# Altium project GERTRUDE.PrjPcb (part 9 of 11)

## Sheet WIFI_BLE.SchDoc: WIFI BLE
size A3; Author: Silvio Navaretti; CompanyName: ARDUINO; DrawnBy: Silvio Navaretti; Engineer: Silvio Navaretti; Organization: ARDUINO; SheetNumber: 29; SheetTotal: 51; RevAuthor: Silvio Navaretti
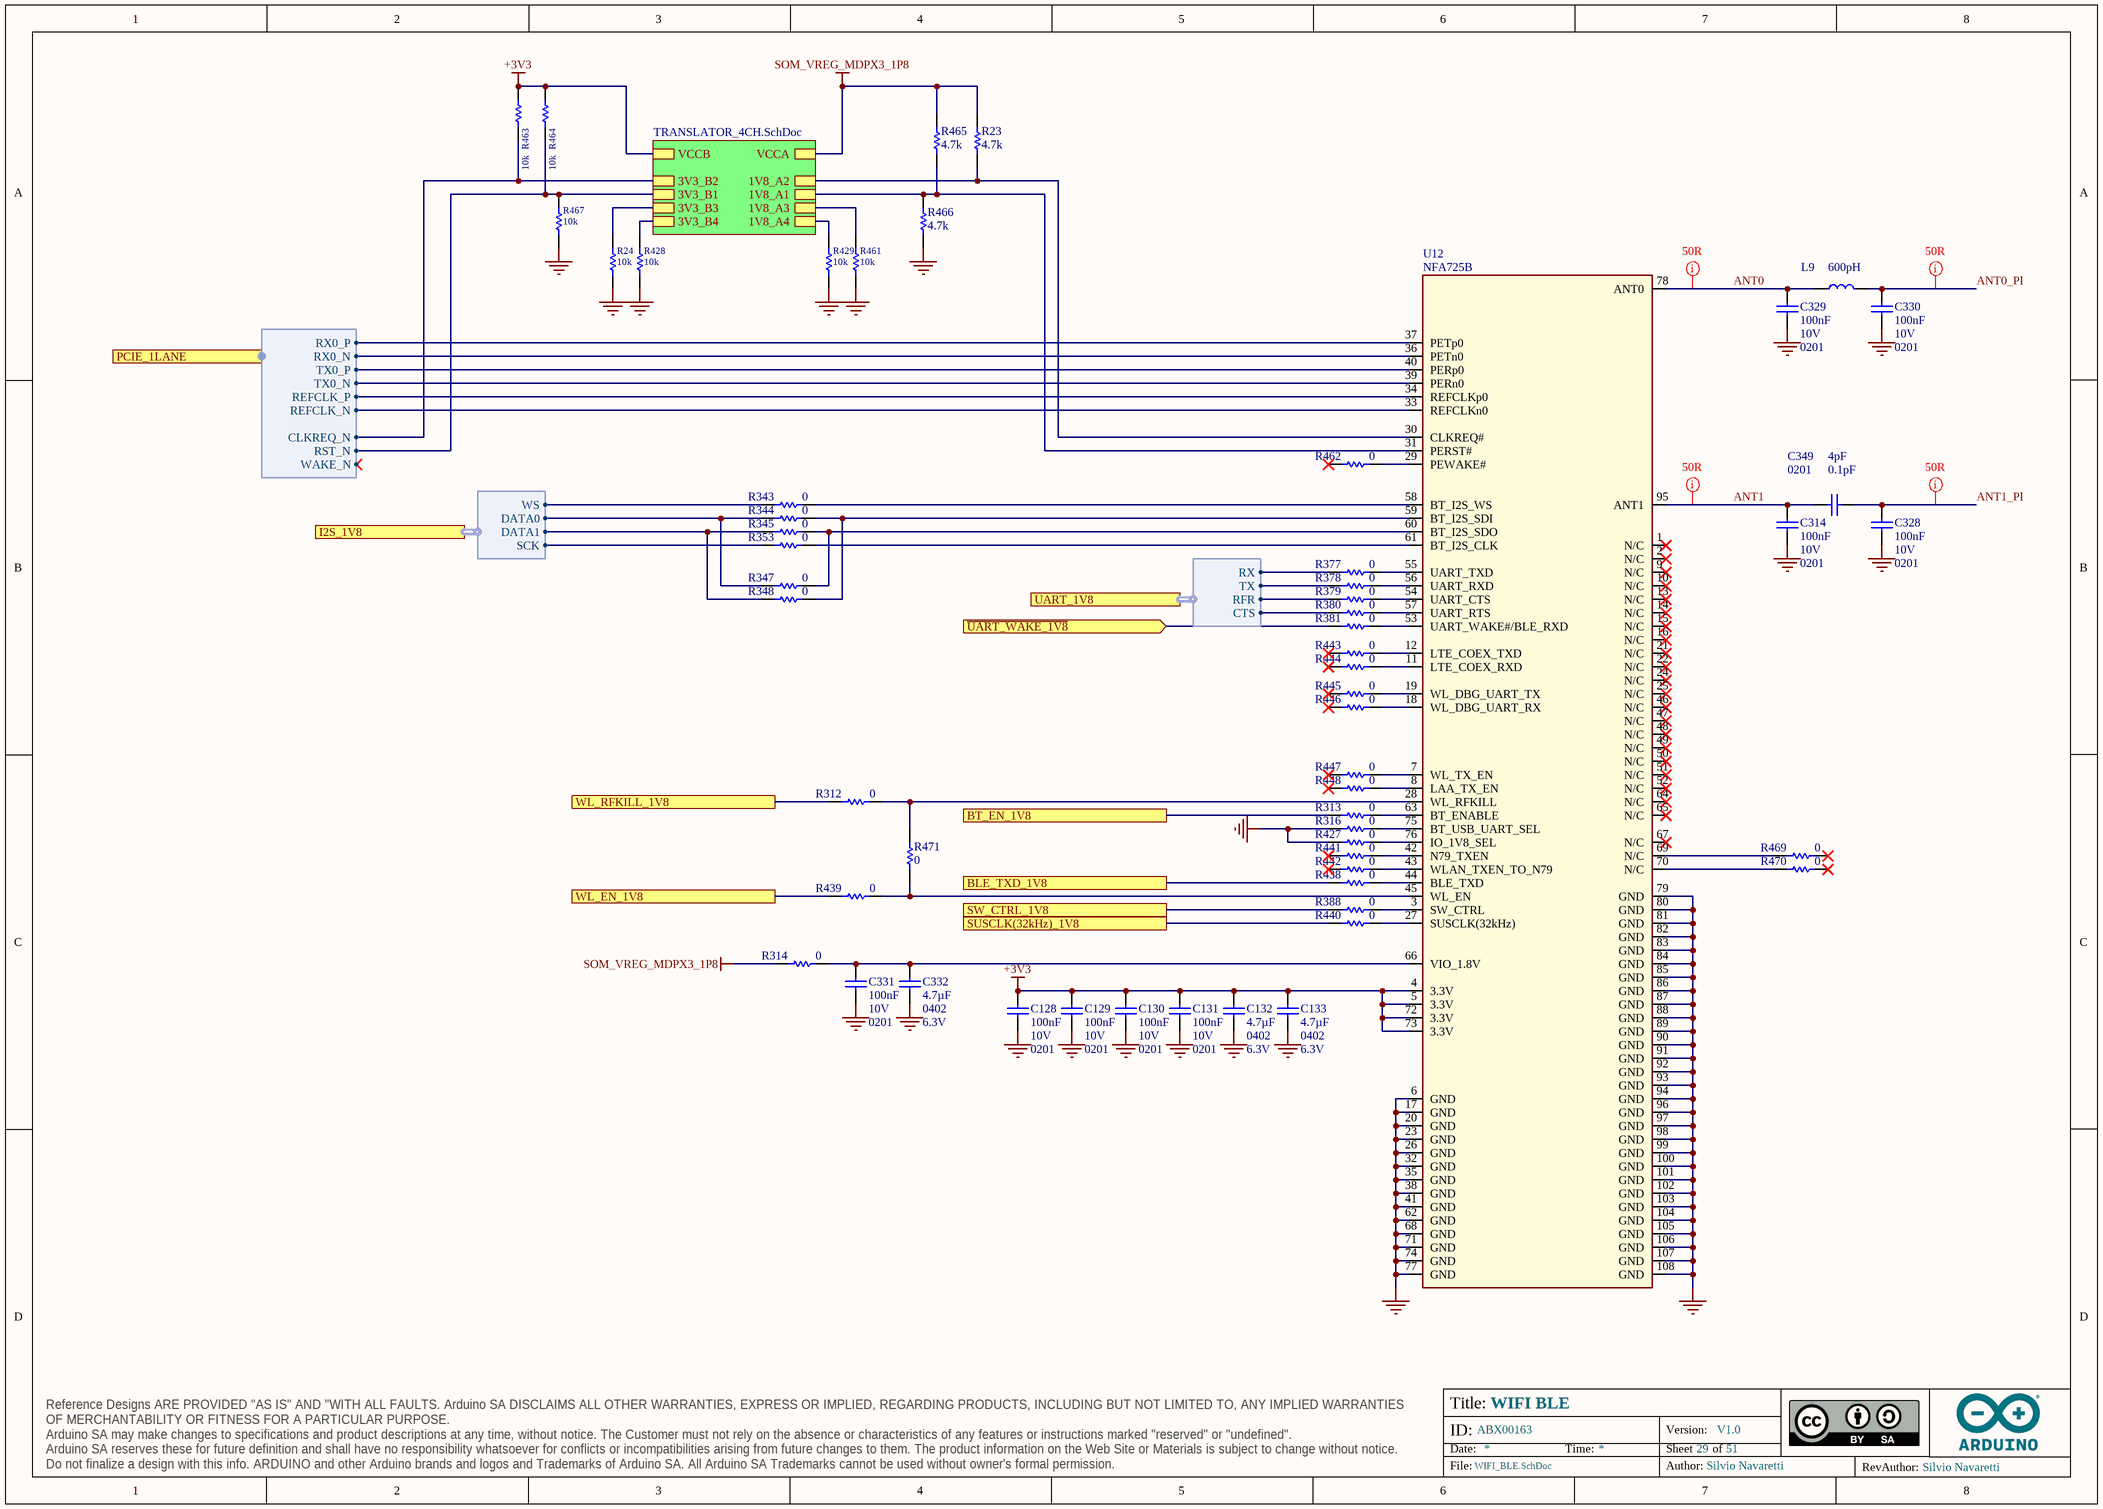
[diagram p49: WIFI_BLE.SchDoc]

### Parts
C128  value 100nF  Voltage: 10V  Case Code (Imperial): 0201  [CAP-0201]  (hidden comment: CL03A104KP3NNNC)
C129  value 100nF  Voltage: 10V  Case Code (Imperial): 0201  [CAP-0201]  (hidden comment: CL03A104KP3NNNC)
C130  value 100nF  Voltage: 10V  Case Code (Imperial): 0201  [CAP-0201]  (hidden comment: CL03A104KP3NNNC)
C131  value 100nF  Voltage: 10V  Case Code (Imperial): 0201  [CAP-0201]  (hidden comment: CL03A104KP3NNNC)
C132  value 4.7µF  Case Code (Imperial): 0402  Voltage: 6.3V  [CAP-0402]  (hidden comment: C1005A475M6R3NT)
C133  value 4.7µF  Case Code (Imperial): 0402  Voltage: 6.3V  [CAP-0402]  (hidden comment: C1005A475M6R3NT)
C314  value 100nF  Voltage: 10V  Case Code (Imperial): 0201  [CAP-0201]  (hidden comment: CL03A104KP3NNNC)
C328  value 100nF  Voltage: 10V  Case Code (Imperial): 0201  [CAP-0201]  (hidden comment: CL03A104KP3NNNC)
C329  value 100nF  Voltage: 10V  Case Code (Imperial): 0201  [CAP-0201]  (hidden comment: CL03A104KP3NNNC)
C330  value 100nF  Voltage: 10V  Case Code (Imperial): 0201  [CAP-0201]  (hidden comment: CL03A104KP3NNNC)
C331  value 100nF  Voltage: 10V  Case Code (Imperial): 0201  [CAP-0201]  (hidden comment: CL03A104KP3NNNC)
C332  value 4.7µF  Case Code (Imperial): 0402  Voltage: 6.3V  [CAP-0402]  (hidden comment: C1005A475M6R3NT)
C349  value 4pF  Case Code (Imperial): 0201  Tolerance: 0.1pF  [CAP-0201]  (hidden comment: GRM0335C1H4R0BA01D)
L9  Inductance: 600pH  [0201DS Coilcraft]  (hidden comment: 0201DS-0N6XKEW)
R23  value 4.7k  [RES-0201]  (hidden comment: RC0201FR-074K7L)
R24  value 10k  [RES-0201]  (hidden comment: RC0201FR-0710KL)
R312  value 0  [RES-0201]  (hidden comment: CRCW02010000Z0ED)
R313  value 0  [RES-0201]  (hidden comment: CRCW02010000Z0ED)
R314  value 0  [RES-0201]  (hidden comment: CRCW02010000Z0ED)
R316  value 0  [RES-0201]  (hidden comment: CRCW02010000Z0ED)
R343  value 0  [RES-0201]  (hidden comment: CRCW02010000Z0ED)
R344  value 0  [RES-0201]  (hidden comment: CRCW02010000Z0ED)
R345  value 0  [RES-0201]  (hidden comment: CRCW02010000Z0ED)
R347  value 0  [RES-0201]  (hidden comment: CRCW02010000Z0ED)
R348  value 0  [RES-0201]  (hidden comment: CRCW02010000Z0ED)
R353  value 0  [RES-0201]  (hidden comment: CRCW02010000Z0ED)
R377  value 0  [RES-0201]  (hidden comment: CRCW02010000Z0ED)
R378  value 0  [RES-0201]  (hidden comment: CRCW02010000Z0ED)
R379  value 0  [RES-0201]  (hidden comment: CRCW02010000Z0ED)
R380  value 0  [RES-0201]  (hidden comment: CRCW02010000Z0ED)
R381  value 0  [RES-0201]  (hidden comment: CRCW02010000Z0ED)
R388  value 0  [RES-0201]  (hidden comment: CRCW02010000Z0ED)
R427  value 0  [RES-0201]  (hidden comment: CRCW02010000Z0ED)
R428  value 10k  [RES-0201]  (hidden comment: RC0201FR-0710KL)
R429  value 10k  [RES-0201]  (hidden comment: RC0201FR-0710KL)
R438  value 0  [RES-0201]  (hidden comment: CRCW02010000Z0ED)
R439  value 0  [RES-0201]  (hidden comment: CRCW02010000Z0ED)
R440  value 0  [RES-0201]  (hidden comment: CRCW02010000Z0ED)
R441  value 0  [RES-0201]  (hidden comment: CRCW02010000Z0ED)
R442  value 0  [RES-0201]  (hidden comment: CRCW02010000Z0ED)
R443  value 0  [RES-0201]  (hidden comment: CRCW02010000Z0ED)
R444  value 0  [RES-0201]  (hidden comment: CRCW02010000Z0ED)
R445  value 0  [RES-0201]  (hidden comment: CRCW02010000Z0ED)
R446  value 0  [RES-0201]  (hidden comment: CRCW02010000Z0ED)
R447  value 0  [RES-0201]  (hidden comment: CRCW02010000Z0ED)
R448  value 0  [RES-0201]  (hidden comment: CRCW02010000Z0ED)
R461  value 10k  [RES-0201]  (hidden comment: RC0201FR-0710KL)
R462  value 0  [RES-0201]  (hidden comment: CRCW02010000Z0ED)
R463  value 10k  [RES-0201]  (hidden comment: RC0201FR-0710KL)
R464  value 10k  [RES-0201]  (hidden comment: RC0201FR-0710KL)
R465  value 4.7k  [RES-0201]  (hidden comment: RC0201FR-074K7L)
R466  value 4.7k  [RES-0201]  (hidden comment: RC0201FR-074K7L)
R467  value 10k  [RES-0201]  (hidden comment: RC0201FR-0710KL)
R469  value 0  [RES-0201]  (hidden comment: CRCW02010000Z0ED)
R470  value 0  [RES-0201]  (hidden comment: CRCW02010000Z0ED)
R471  value 0  [RES-0201]  (hidden comment: CRCW02010000Z0ED)
U12  NFA725B  [NFA725B]

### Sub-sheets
U_TRANSLATOR_4CH = TRANSLATOR_4CH.SchDoc: 1V8_A1, 1V8_A2, 1V8_A3, 1V8_A4, 3V3_B1, 3V3_B2, 3V3_B3, 3V3_B4, VCCA, VCCB

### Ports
BLE_TXD_1V8, BT_EN_1V8, I2S_1V8 (harness SOM_MD_I2S), PCIE_1LANE (harness PCIE_1LANE), SUSCLK(32kHz)_1V8, SW_CTRL_1V8, UART_1V8 (harness SOM_MD_UART_FLCRTL), WL_EN_1V8, WL_RFKILL_1V8, ~{UART_WAKE_1V8} (in)

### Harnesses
SOM_MD_I2S: SCK, WS, DATA0, DATA1
SOM_MD_UART_FLCRTL: TX, CTS, RFR, RX
PCIE_1LANE: RX0_N, RX0_P, TX0_P, TX0_N, REFCLK_N, REFCLK_P, WAKE_N, CLKREQ_N, RST_N

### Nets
+3V3: C128.2 C129.2 C130.2 C131.2 C132.1 C133.1 R463.1 R464.1 U12.4(3.3V) U12.5(3.3V) U12.72(3.3V) U12.73(3.3V) ; sheet U_TRANSLATOR_4CH/VCCB
GND: C128.1 C129.1 C130.1 C131.1 C132.2 C133.2 C314.1 C328.1 C329.1 C330.1 C331.1 C332.2 R24.1 R316.1 R427.1 R428.1 R429.1 R461.1 R466.1 R467.1 U12.6(GND) U12.17(GND) U12.20(GND) U12.23(GND) U12.26(GND) U12.32(GND) U12.35(GND) U12.38(GND) U12.41(GND) U12.62(GND) U12.68(GND) U12.71(GND) U12.74(GND) U12.77(GND) U12.79(GND) U12.80(GND) U12.81(GND) U12.82(GND) U12.83(GND) U12.84(GND) U12.85(GND) U12.86(GND) U12.87(GND) U12.88(GND) U12.89(GND) U12.90(GND) U12.91(GND) U12.92(GND) U12.93(GND) U12.94(GND) U12.96(GND) U12.97(GND) U12.98(GND) U12.99(GND) U12.100(GND) U12.101(GND) U12.102(GND) U12.103(GND) U12.104(GND) U12.105(GND) U12.106(GND) U12.107(GND) U12.108(GND)
SOM_VREG_MDPX3_1P8: R23.2 R314.1 R465.2 ; sheet U_TRANSLATOR_4CH/VCCA
ANT0: C329.2 L9.1 U12.78(ANT0)  [project net ANT0_29]
ANT0_PI: C330.2 L9.2  [project net ANT0_PI_29]
ANT1: C314.2 C349.2 U12.95(ANT1)  [project net ANT1_29]
ANT1_PI: C328.2 C349.1  [project net ANT1_PI_29]
CTS_1V8: R380.1 ; port UART_1V8.CTS
MD_GPIO_54: R312.1 ; port WL_RFKILL_1V8
MD_GPIO_55: R313.1 ; port BT_EN_1V8
MD_GPIO_56: R439.1 ; port WL_EN_1V8
MD_GPIO_65: R381.1 ; port ~{UART_WAKE_1V8}
MD_GPIO_85: R379.1 ; port UART_1V8.RFR
MD_GPIO_86: R378.1 ; port UART_1V8.TX
MD_GPIO_87: R377.1 ; port UART_1V8.RX
MD_GPIO_100: R388.1 ; port SW_CTRL_1V8
MD_GPIO_101: R438.1 ; port BLE_TXD_1V8
MD_LPASS_GPIO_129: R353.1 ; port I2S_1V8.SCK
MD_LPASS_GPIO_130: R343.1 ; port I2S_1V8.WS
MD_LPASS_GPIO_131: R344.1 R347.1 ; port I2S_1V8.DATA0
MD_LPASS_GPIO_132: R345.1 R348.1 ; port I2S_1V8.DATA1
PCIE1_REFCLK0_N: U12.33(REFCLKn0) ; port PCIE_1LANE.REFCLK_N
PCIE1_REFCLK0_P: U12.34(REFCLKp0) ; port PCIE_1LANE.REFCLK_P
PCIE1_RX0_N: U12.36(PETn0) ; port PCIE_1LANE.RX0_N
PCIE1_RX0_P: U12.37(PETp0) ; port PCIE_1LANE.RX0_P
PCIE1_TX0_CAP_N: U12.39(PERn0) ; port PCIE_1LANE.TX0_N
PCIE1_TX0_CAP_P: U12.40(PERp0) ; port PCIE_1LANE.TX0_P
SLEEP_CLK: R440.1 ; port SUSCLK(32kHz)_1V8
NetC331_2: C331.2 C332.1 R314.2 U12.66(VIO_1.8V)
NetR23_1: R23.1 U12.30(CLKREQ#) ; sheet U_TRANSLATOR_4CH/1V8_A2
NetR24_2: R24.2 ; sheet U_TRANSLATOR_4CH/3V3_B3
NetR312_2: R312.2 R471.1 U12.28(WL_RFKILL)
NetR313_2: R313.2 U12.63(BT_ENABLE)
NetR316_2: R316.2 U12.75(BT_USB_UART_SEL)
NetR343_2: R343.2 U12.58(BT_I2S_WS)
NetR344_2: R344.2 R348.2 U12.59(BT_I2S_SDI)
NetR345_2: R345.2 R347.2 U12.60(BT_I2S_SDO)
NetR353_2: R353.2 U12.61(BT_I2S_CLK)
NetR377_2: R377.2 U12.55(UART_TXD)
NetR378_2: R378.2 U12.56(UART_RXD)
NetR379_2: R379.2 U12.54(UART_CTS)
NetR380_2: R380.2 U12.57(UART_RTS)
NetR381_2: R381.2 U12.53(UART_WAKE#/BLE_RXD)
NetR388_2: R388.2 U12.3(SW_CTRL)
NetR427_2: R427.2 U12.76(IO_1V8_SEL)
NetR428_2: R428.2 ; sheet U_TRANSLATOR_4CH/3V3_B4
NetR429_2: R429.2 ; sheet U_TRANSLATOR_4CH/1V8_A4
NetR438_2: R438.2 U12.44(BLE_TXD)
NetR439_2: R439.2 R471.2 U12.45(WL_EN)
NetR440_2: R440.2 U12.27(SUSCLK(32kHz))
NetR441_2: R441.2 U12.42(N79_TXEN)
NetR442_2: R442.2 U12.43(WLAN_TXEN_TO_N79)
NetR443_2: R443.2 U12.12(LTE_COEX_TXD)
NetR444_2: R444.2 U12.11(LTE_COEX_RXD)
NetR445_2: R445.2 U12.19(WL_DBG_UART_TX)
NetR446_2: R446.2 U12.18(WL_DBG_UART_RX)
NetR447_2: R447.2 U12.7(WL_TX_EN)
NetR448_2: R448.2 U12.8(LAA_TX_EN)
NetR461_2: R461.2 ; sheet U_TRANSLATOR_4CH/1V8_A3
NetR462_2: R462.2 U12.29(PEWAKE#)
NetR463_2: R463.2 ; sheet U_TRANSLATOR_4CH/3V3_B2, port PCIE_1LANE.CLKREQ_N
NetR464_2: R464.2 R467.2 ; sheet U_TRANSLATOR_4CH/3V3_B1, port PCIE_1LANE.RST_N
NetR465_1: R465.1 R466.2 U12.31(PERST#) ; sheet U_TRANSLATOR_4CH/1V8_A1
NetR469_1: R469.1 U12.69(N/C)
NetR470_1: R470.1 U12.70(N/C)

Not connected (* = marked no-connect by the designer): R441 1*; R442 1*; R443 1*; R444 1*; R445 1*; R446 1*; R447 1*; R448 1*; R462 1*; R469 2*; R470 2*; U12 1(N/C)* 2(N/C)* 9(N/C)* 10(N/C)* 13(N/C)* 14(N/C)* 15(N/C)* 16(N/C)* 21(N/C)* 22(N/C)* 24(N/C)* 25(N/C)* 46(N/C)* 47(N/C)* 48(N/C)* 49(N/C)* 50(N/C)* 51(N/C)* 52(N/C)* 64(N/C)* 65(N/C)* 67(N/C)*

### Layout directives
net class 50R: ANT0_29, ANT0_PI_29, ANT1_29, ANT1_PI_29

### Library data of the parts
C128-C131 C314 C328-C331 = C0113-A.6: CAP CHIP 0201 100nF 10% 10V X5R; Manufacturer: Samsung Electro-Mechanics; Code Arduino: C0113
C132 C133 C332 = C0037-A.14: CAP CHIP 0402 4.7uF 20% 6V3 X5R; Manufacturer: Hottech; Code Arduino: 0833
C349 = C0210-A.1: CAP CHIP 0201 4pF 0.1pF 50V C0G; Manufacturer: Murata; Code Arduino: C0210
L9 = I0132-A.2: IND 0201 0.6nH 1A 30mR; Code Arduino: I0132; DCR max: 30m
R23 R465 R466 = R0151-A.21: RES CHIP 0201 4k7 1% 1/20W; Manufacturer: Yageo; Power: 50mW; Temperature coefficient: 200ppm; Code Arduino: A5521
R24 R428 R429 R461 R463 R464 R467 = R0145-A.21: RES CHIP 0201 10k 1% 1/20W; Manufacturer: Yageo; Power: 50mW; Temperature coefficient: 200ppm; Code Arduino: R0145
R312-R314 R316 R343-R345 R347 R348 R353 R377-R381 R388 R427 R438-R448 R462 R469-R471 = R0140-A.21: RES CHIP 0201 0R; Manufacturer: Vishay; Temperature coefficient: 0ppm; Code Arduino: R0140; Power: 50mW; Tolerance: 0%
U12 = M0030-A.15: Module 802.11a/b/g/n/ac/ax 2x2 MAC + BT 5.2, QCA2066, with 2 antenna pads, PCIe, LGA76 14x17.68mm; Manufacturer: USI; Code Arduino: M0030

## Sheet PCIE_USB.SchDoc: PCIE_USB
size A3; Author: Silvio Navaretti; CompanyName: ARDUINO; DrawnBy: Silvio Navaretti; Engineer: Silvio Navaretti; Organization: ARDUINO; SheetNumber: 26; SheetTotal: 51; RevAuthor: Silvio Navaretti
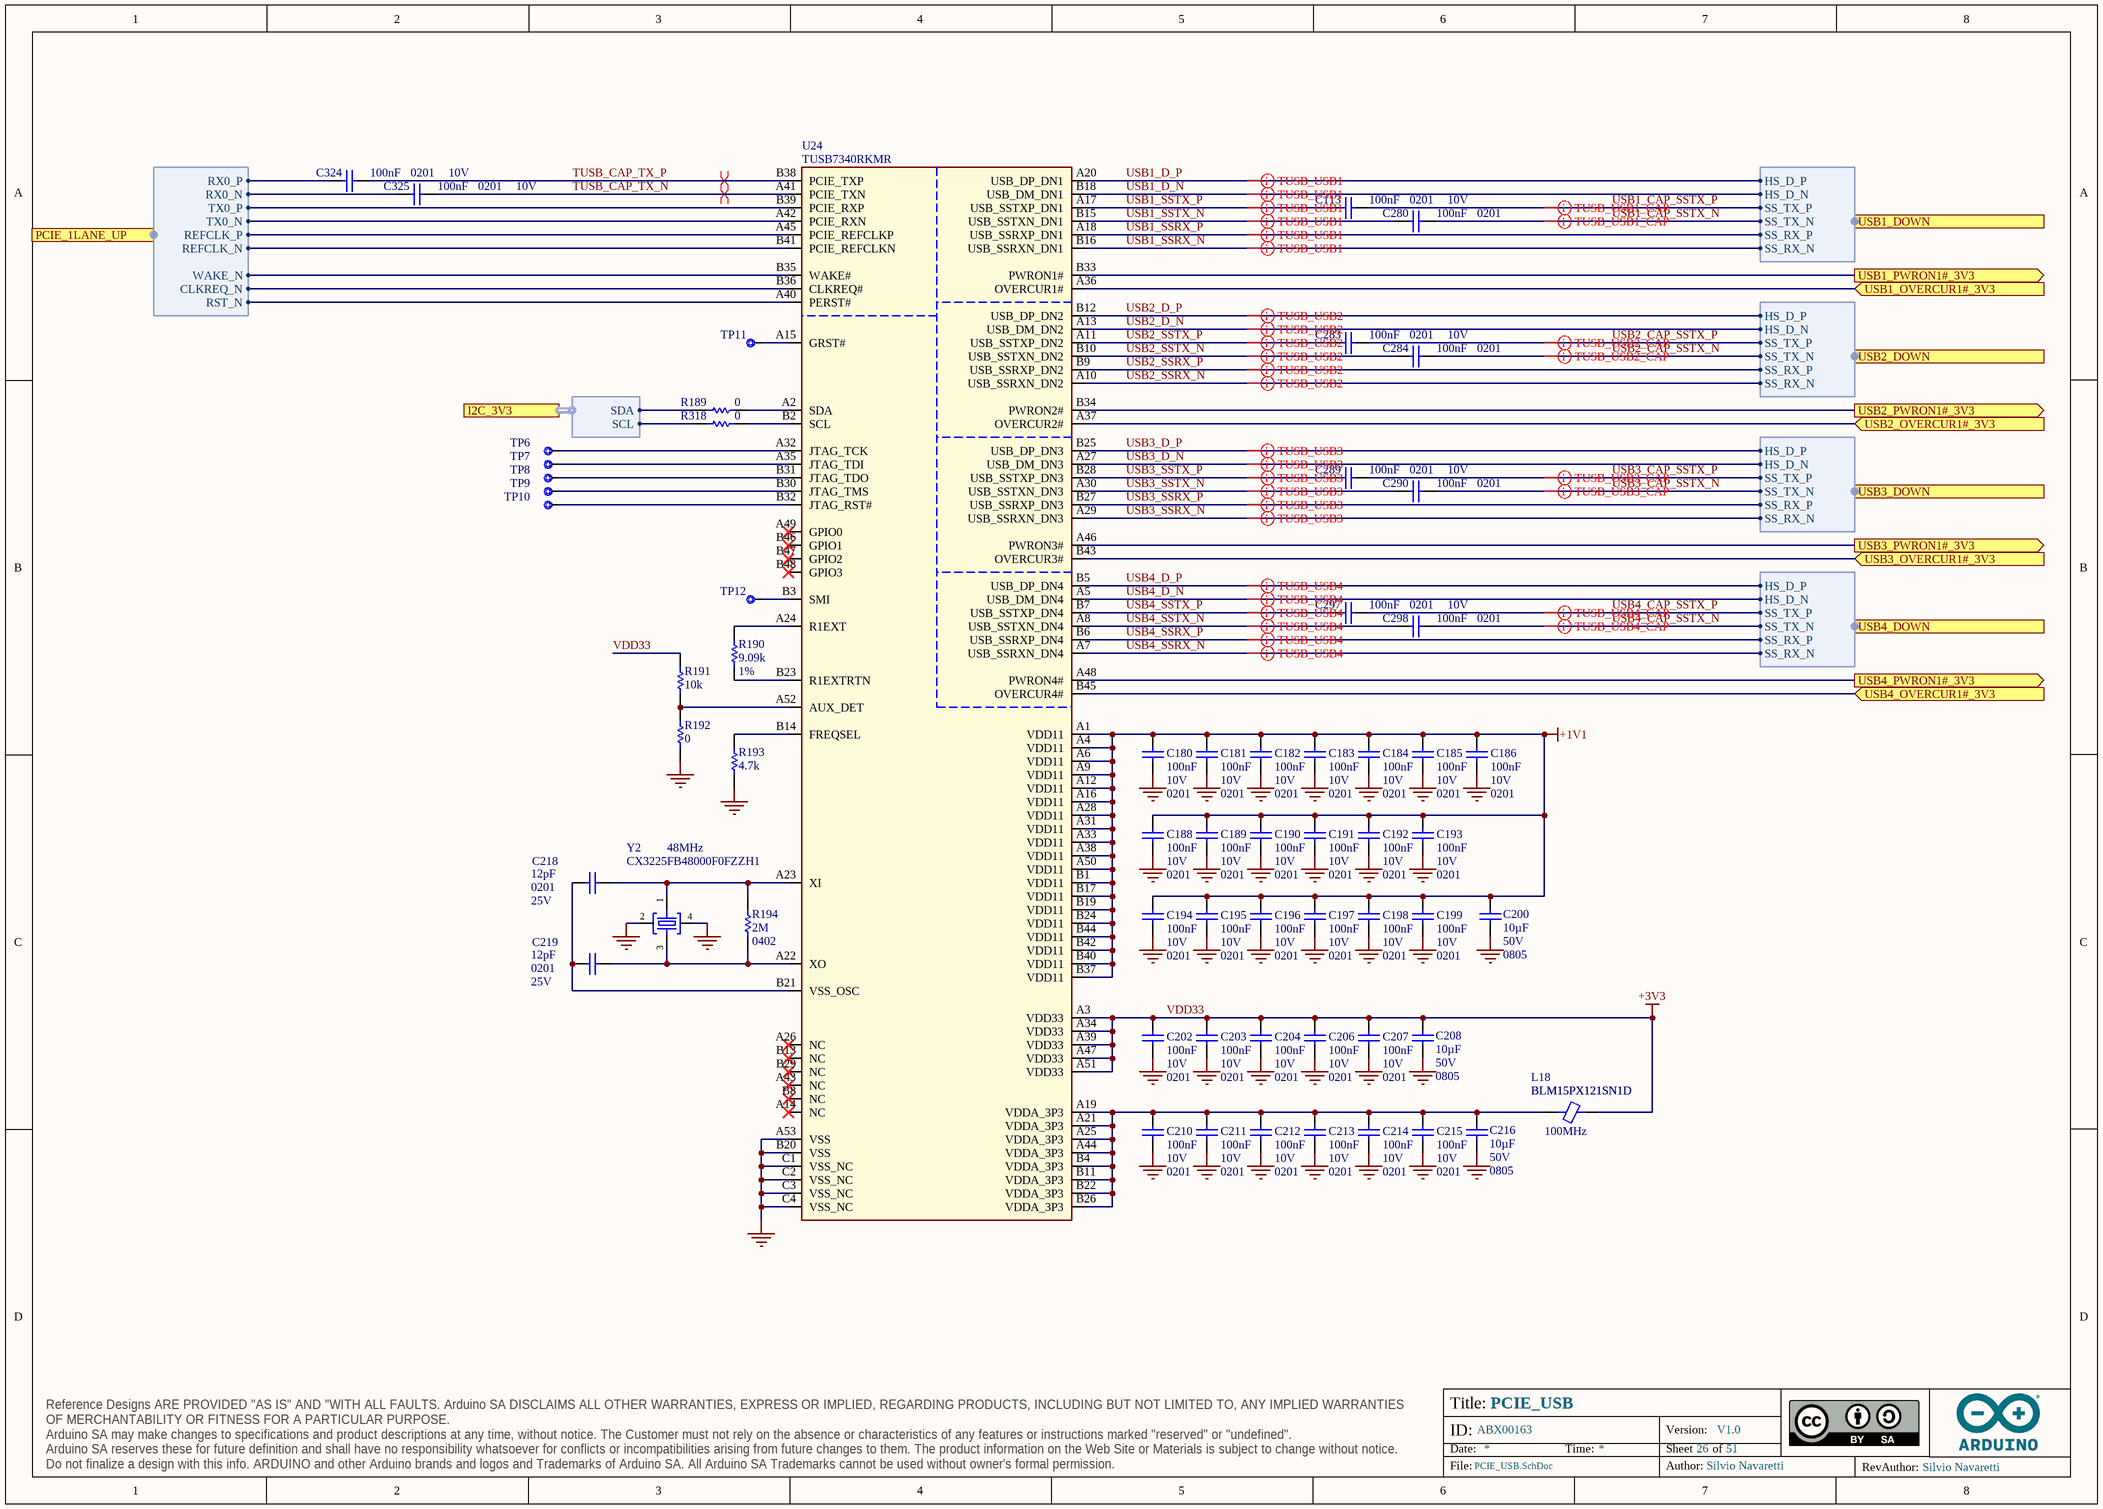
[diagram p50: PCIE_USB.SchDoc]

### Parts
C113  value 100nF  Case Code (Imperial): 0201  Voltage: 10V  [CAP-0201]  (hidden comment: CL03A104KP3NNNC)
C180  value 100nF  Voltage: 10V  Case Code (Imperial): 0201  [CAP-0201]  (hidden comment: CL03A104KP3NNNC)
C181  value 100nF  Voltage: 10V  Case Code (Imperial): 0201  [CAP-0201]  (hidden comment: CL03A104KP3NNNC)
C182  value 100nF  Voltage: 10V  Case Code (Imperial): 0201  [CAP-0201]  (hidden comment: CL03A104KP3NNNC)
C183  value 100nF  Voltage: 10V  Case Code (Imperial): 0201  [CAP-0201]  (hidden comment: CL03A104KP3NNNC)
C184  value 100nF  Voltage: 10V  Case Code (Imperial): 0201  [CAP-0201]  (hidden comment: CL03A104KP3NNNC)
C185  value 100nF  Voltage: 10V  Case Code (Imperial): 0201  [CAP-0201]  (hidden comment: CL03A104KP3NNNC)
C186  value 100nF  Voltage: 10V  Case Code (Imperial): 0201  [CAP-0201]  (hidden comment: CL03A104KP3NNNC)
C188  value 100nF  Voltage: 10V  Case Code (Imperial): 0201  [CAP-0201]  (hidden comment: CL03A104KP3NNNC)
C189  value 100nF  Voltage: 10V  Case Code (Imperial): 0201  [CAP-0201]  (hidden comment: CL03A104KP3NNNC)
C190  value 100nF  Voltage: 10V  Case Code (Imperial): 0201  [CAP-0201]  (hidden comment: CL03A104KP3NNNC)
C191  value 100nF  Voltage: 10V  Case Code (Imperial): 0201  [CAP-0201]  (hidden comment: CL03A104KP3NNNC)
C192  value 100nF  Voltage: 10V  Case Code (Imperial): 0201  [CAP-0201]  (hidden comment: CL03A104KP3NNNC)
C193  value 100nF  Voltage: 10V  Case Code (Imperial): 0201  [CAP-0201]  (hidden comment: CL03A104KP3NNNC)
C194  value 100nF  Voltage: 10V  Case Code (Imperial): 0201  [CAP-0201]  (hidden comment: CL03A104KP3NNNC)
C195  value 100nF  Voltage: 10V  Case Code (Imperial): 0201  [CAP-0201]  (hidden comment: CL03A104KP3NNNC)
C196  value 100nF  Voltage: 10V  Case Code (Imperial): 0201  [CAP-0201]  (hidden comment: CL03A104KP3NNNC)
C197  value 100nF  Voltage: 10V  Case Code (Imperial): 0201  [CAP-0201]  (hidden comment: CL03A104KP3NNNC)
C198  value 100nF  Voltage: 10V  Case Code (Imperial): 0201  [CAP-0201]  (hidden comment: CL03A104KP3NNNC)
C199  value 100nF  Voltage: 10V  Case Code (Imperial): 0201  [CAP-0201]  (hidden comment: CL03A104KP3NNNC)
C200  value 10µF  Voltage: 50V  Case Code (Imperial): 0805  [CAP-0805]  (hidden comment: GRM21BR61H106ME43L)
C202  value 100nF  Voltage: 10V  Case Code (Imperial): 0201  [CAP-0201]  (hidden comment: CL03A104KP3NNNC)
C203  value 100nF  Voltage: 10V  Case Code (Imperial): 0201  [CAP-0201]  (hidden comment: CL03A104KP3NNNC)
C204  value 100nF  Voltage: 10V  Case Code (Imperial): 0201  [CAP-0201]  (hidden comment: CL03A104KP3NNNC)
C206  value 100nF  Voltage: 10V  Case Code (Imperial): 0201  [CAP-0201]  (hidden comment: CL03A104KP3NNNC)
C207  value 100nF  Voltage: 10V  Case Code (Imperial): 0201  [CAP-0201]  (hidden comment: CL03A104KP3NNNC)
C208  value 10µF  Voltage: 50V  Case Code (Imperial): 0805  [CAP-0805]  (hidden comment: GRM21BR61H106ME43L)
C210  value 100nF  Voltage: 10V  Case Code (Imperial): 0201  [CAP-0201]  (hidden comment: CL03A104KP3NNNC)
C211  value 100nF  Voltage: 10V  Case Code (Imperial): 0201  [CAP-0201]  (hidden comment: CL03A104KP3NNNC)
C212  value 100nF  Voltage: 10V  Case Code (Imperial): 0201  [CAP-0201]  (hidden comment: CL03A104KP3NNNC)
C213  value 100nF  Voltage: 10V  Case Code (Imperial): 0201  [CAP-0201]  (hidden comment: CL03A104KP3NNNC)
C214  value 100nF  Voltage: 10V  Case Code (Imperial): 0201  [CAP-0201]  (hidden comment: CL03A104KP3NNNC)
C215  value 100nF  Voltage: 10V  Case Code (Imperial): 0201  [CAP-0201]  (hidden comment: CL03A104KP3NNNC)
C216  value 10µF  Voltage: 50V  Case Code (Imperial): 0805  [CAP-0805]  (hidden comment: GRM21BR61H106ME43L)
C218  value 12pF  Case Code (Imperial): 0201  Voltage: 25V  [CAP-0201]  (hidden comment: GRM0335C1E120JA01J)
C219  value 12pF  Case Code (Imperial): 0201  Voltage: 25V  [CAP-0201]  (hidden comment: GRM0335C1E120JA01J)
C280  value 100nF  Case Code (Imperial): 0201  [CAP-0201]  (hidden comment: CL03A104KP3NNNC)
C283  value 100nF  Case Code (Imperial): 0201  Voltage: 10V  [CAP-0201]  (hidden comment: CL03A104KP3NNNC)
C284  value 100nF  Case Code (Imperial): 0201  [CAP-0201]  (hidden comment: CL03A104KP3NNNC)
C289  value 100nF  Case Code (Imperial): 0201  Voltage: 10V  [CAP-0201]  (hidden comment: CL03A104KP3NNNC)
C290  value 100nF  Case Code (Imperial): 0201  [CAP-0201]  (hidden comment: CL03A104KP3NNNC)
C297  value 100nF  Case Code (Imperial): 0201  Voltage: 10V  [CAP-0201]  (hidden comment: CL03A104KP3NNNC)
C298  value 100nF  Case Code (Imperial): 0201  [CAP-0201]  (hidden comment: CL03A104KP3NNNC)
C324  value 100nF  Case Code (Imperial): 0201  Voltage: 10V  [CAP-0201]  (hidden comment: CL03A104KP3NNNC)
C325  value 100nF  Case Code (Imperial): 0201  Voltage: 10V  [CAP-0201]  (hidden comment: CL03A104KP3NNNC)
L18  BLM15PX121SN1D  Test Frequency: 100MHz  [L-0402]
R189  value 0  [RES-0201]  (hidden comment: CRCW02010000Z0ED)
R190  value 9.09k  Tolerance: 1%  [RES-0201]  (hidden comment: RC0201FR-079K09L)
R191  value 10k  [RES-0201]  (hidden comment: RC0201FR-0710KL)
R192  value 0  [RES-0201]  (hidden comment: CRCW02010000Z0ED)
R193  value 4.7k  [RES-0201]  (hidden comment: RC0201FR-074K7L)
R194  value 2M  Case Code (Imperial): 0402  [RES-0402]  (hidden comment: RC0402FR-072ML)
R318  value 0  [RES-0201]  (hidden comment: CRCW02010000Z0ED)
TP6  Test point 1.00mm  [TP-1.00MM]  (value not drawn)  (no BOM)
TP7  Test point 1.00mm  [TP-1.00MM]  (value not drawn)  (no BOM)
TP8  Test point 1.00mm  [TP-1.00MM]  (value not drawn)  (no BOM)
TP9  Test point 1.00mm  [TP-1.00MM]  (value not drawn)  (no BOM)
TP10  Test point 1.00mm  [TP-1.00MM]  (value not drawn)  (no BOM)
TP11  Test point 1.00mm  [TP-1.00MM]  (value not drawn)  (no BOM)
TP12  Test point 1.00mm  [TP-1.00MM]  (value not drawn)  (no BOM)
U24  TUSB7340RKMR  [TI RKM S-PWQFN-N100 Double row 9x9mm pitch 0.6mm]
Y2  CX3225FB48000F0FZZH1  Frequency: 48MHz  [CRYSTAL3.2X2.5]

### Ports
I2C_3V3 (harness I2C), PCIE_1LANE_UP (harness PCIE_1LANE), USB1_DOWN (harness SOM_MD_USB0), USB1_OVERCUR1#_3V3 (in), USB1_PWRON1#_3V3 (out), USB2_DOWN (harness SOM_MD_USB0), USB2_OVERCUR1#_3V3 (in), USB2_PWRON1#_3V3 (out), USB3_DOWN (harness SOM_MD_USB0), USB3_OVERCUR1#_3V3 (in), USB3_PWRON1#_3V3 (out), USB4_DOWN (harness SOM_MD_USB0), USB4_OVERCUR1#_3V3 (in), USB4_PWRON1#_3V3 (out)

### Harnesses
SOM_MD_USB0: SS_TX_N, SS_TX_P, HS_D_P, HS_D_N, SS_RX_P, SS_RX_N
PCIE_1LANE: RX0_N, RX0_P, TX0_P, TX0_N, REFCLK_N, REFCLK_P, WAKE_N, CLKREQ_N, RST_N
I2C: SDA, SCL

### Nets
+1V1: C180.2 C181.2 C182.2 C183.2 C184.2 C185.2 C186.2 C188.2 C189.2 C190.2 C191.2 C192.2 C193.2 C194.2 C195.2 C196.2 C197.2 C198.2 C199.2 C200.2 U24.A1(VDD11) U24.A4(VDD11) U24.A6(VDD11) U24.A9(VDD11) U24.A12(VDD11) U24.A16(VDD11) U24.A28(VDD11) U24.A31(VDD11) U24.A33(VDD11) U24.A38(VDD11) U24.A50(VDD11) U24.B1(VDD11) U24.B17(VDD11) U24.B19(VDD11) U24.B24(VDD11) U24.B37(VDD11) U24.B40(VDD11) U24.B42(VDD11) U24.B44(VDD11)
+3V3: C202.2 C203.2 C204.2 C206.2 C207.2 C208.2 L18.2 R191.2 U24.A3(VDD33) U24.A34(VDD33) U24.A39(VDD33) U24.A47(VDD33) U24.A51(VDD33)  [also labelled VDD33]
GND: C180.1 C181.1 C182.1 C183.1 C184.1 C185.1 C186.1 C188.1 C189.1 C190.1 C191.1 C192.1 C193.1 C194.1 C195.1 C196.1 C197.1 C198.1 C199.1 C200.1 C202.1 C203.1 C204.1 C206.1 C207.1 C208.1 C210.1 C211.1 C212.1 C213.1 C214.1 C215.1 C216.1 R192.2 R193.2 U24.A53(VSS) U24.B20(VSS) U24.C1(VSS_NC) U24.C2(VSS_NC) U24.C3(VSS_NC) U24.C4(VSS_NC) Y2.2 Y2.4
MD_QUP1_SE4_I2C_3V3.SCL: R318.1 ; port I2C_3V3.SCL
MD_QUP1_SE4_I2C_3V3.SDA: R189.1 ; port I2C_3V3.SDA
PCIE2_REFCLK0_N: U24.B41(PCIE_REFCLKN) ; port PCIE_1LANE_UP.REFCLK_N
PCIE2_REFCLK0_P: U24.A45(PCIE_REFCLKP) ; port PCIE_1LANE_UP.REFCLK_P
PCIE2_RX0_N: C325.1 ; port PCIE_1LANE_UP.RX0_N
PCIE2_RX0_P: C324.1 ; port PCIE_1LANE_UP.RX0_P
PCIE2_TX0_CAP_N: U24.A42(PCIE_RXN) ; port PCIE_1LANE_UP.TX0_N
PCIE2_TX0_CAP_P: U24.B39(PCIE_RXP) ; port PCIE_1LANE_UP.TX0_P
TUSB_CAP_TX_N: C325.2 U24.A41(PCIE_TXN)  [project net TUSB_CAP_TX_N_26]
TUSB_CAP_TX_P: C324.2 U24.B38(PCIE_TXP)  [project net TUSB_CAP_TX_P_26]
USB1_CAP_SSTX_N: C280.2 ; port USB1_DOWN.SS_TX_N
USB1_CAP_SSTX_P: C113.2 ; port USB1_DOWN.SS_TX_P
USB1_D_N: U24.B18(USB_DM_DN1) ; port USB1_DOWN.HS_D_N
USB1_D_P: U24.A20(USB_DP_DN1) ; port USB1_DOWN.HS_D_P
USB1_SSRX_N: U24.B16(USB_SSRXN_DN1) ; port USB1_DOWN.SS_RX_N
USB1_SSRX_P: U24.A18(USB_SSRXP_DN1) ; port USB1_DOWN.SS_RX_P
USB1_SSTX_N: C280.1 U24.B15(USB_SSTXN_DN1)  [project net USB1_SSTX_N_26]
USB1_SSTX_P: C113.1 U24.A17(USB_SSTXP_DN1)  [project net USB1_SSTX_P_26]
USB2_CAP_SSTX_N: C284.2 ; port USB2_DOWN.SS_TX_N
USB2_CAP_SSTX_P: C283.2 ; port USB2_DOWN.SS_TX_P
USB2_D_N: U24.A13(USB_DM_DN2) ; port USB2_DOWN.HS_D_N
USB2_D_P: U24.B12(USB_DP_DN2) ; port USB2_DOWN.HS_D_P
USB2_SSRX_N: U24.A10(USB_SSRXN_DN2) ; port USB2_DOWN.SS_RX_N
USB2_SSRX_P: U24.B9(USB_SSRXP_DN2) ; port USB2_DOWN.SS_RX_P
USB2_SSTX_N: C284.1 U24.B10(USB_SSTXN_DN2)  [project net USB2_SSTX_N_26]
USB2_SSTX_P: C283.1 U24.A11(USB_SSTXP_DN2)  [project net USB2_SSTX_P_26]
USB3_CAP_SSTX_N: C290.2 ; port USB3_DOWN.SS_TX_N
USB3_CAP_SSTX_P: C289.2 ; port USB3_DOWN.SS_TX_P
USB3_D_N: U24.A27(USB_DM_DN3) ; port USB3_DOWN.HS_D_N
USB3_D_P: U24.B25(USB_DP_DN3) ; port USB3_DOWN.HS_D_P
USB3_SSRX_N: U24.A29(USB_SSRXN_DN3) ; port USB3_DOWN.SS_RX_N
USB3_SSRX_P: U24.B27(USB_SSRXP_DN3) ; port USB3_DOWN.SS_RX_P
USB3_SSTX_N: C290.1 U24.A30(USB_SSTXN_DN3)  [project net USB3_SSTX_N_26]
USB3_SSTX_P: C289.1 U24.B28(USB_SSTXP_DN3)  [project net USB3_SSTX_P_26]
USB4_CAP_SSTX_N: C298.2 ; port USB4_DOWN.SS_TX_N
USB4_CAP_SSTX_P: C297.2 ; port USB4_DOWN.SS_TX_P
USB4_D_N: U24.A5(USB_DM_DN4) ; port USB4_DOWN.HS_D_N
USB4_D_P: U24.B5(USB_DP_DN4) ; port USB4_DOWN.HS_D_P
USB4_SSRX_N: U24.A7(USB_SSRXN_DN4) ; port USB4_DOWN.SS_RX_N
USB4_SSRX_P: U24.B6(USB_SSRXP_DN4) ; port USB4_DOWN.SS_RX_P
USB4_SSTX_N: C298.1 U24.A8(USB_SSTXN_DN4)  [project net USB4_SSTX_N_26]
USB4_SSTX_P: C297.1 U24.B7(USB_SSTXP_DN4)  [project net USB4_SSTX_P_26]
NetC210_2: C210.2 C211.2 C212.2 C213.2 C214.2 C215.2 C216.2 L18.1 U24.A19(VDDA_3P3) U24.A21(VDDA_3P3) U24.A25(VDDA_3P3) U24.A44(VDDA_3P3) U24.B4(VDDA_3P3) U24.B11(VDDA_3P3) U24.B22(VDDA_3P3) U24.B26(VDDA_3P3)
NetC218_1: C218.1 R194.2 U24.A23(XI) Y2.1
NetC218_2: C218.2 C219.2 U24.B21(VSS_OSC)
NetC219_1: C219.1 R194.1 U24.A22(XO) Y2.3
NetJOMEGA_54: U24.B33(PWRON1#) ; port USB1_PWRON1#_3V3
NetJOMEGA_56: U24.A36(OVERCUR1#) ; port USB1_OVERCUR1#_3V3
NetJOMEGA_58: U24.A46(PWRON3#) ; port USB3_PWRON1#_3V3
NetJOMEGA_60: U24.B43(OVERCUR3#) ; port USB3_OVERCUR1#_3V3
NetR154_2: U24.A48(PWRON4#) ; port USB4_PWRON1#_3V3
NetR182_2: U24.B34(PWRON2#) ; port USB2_PWRON1#_3V3
NetR189_2: R189.2 U24.A2(SDA)
NetR190_1: R190.1 U24.A24(R1EXT)
NetR190_2: R190.2 U24.B23(R1EXTRTN)
NetR191_1: R191.1 R192.1 U24.A52(AUX_DET)
NetR193_1: R193.1 U24.B14(FREQSEL)
NetR318_2: R318.2 U24.B2(SCL)
NetTP6_X: TP6.X U24.A32(JTAG_TCK)
NetTP7_X: TP7.X U24.A35(JTAG_TDI)
NetTP8_X: TP8.X U24.B31(JTAG_TDO)
NetTP9_X: TP9.X U24.B30(JTAG_TMS)
NetTP10_X: TP10.X U24.B32(JTAG_RST#)
NetTP11_X: TP11.X U24.A15(GRST#)
NetTP12_X: TP12.X U24.B3(SMI)
NetU24_A37: U24.A37(OVERCUR2#) ; port USB2_OVERCUR1#_3V3
NetU24_A40: U24.A40(PERST#) ; port PCIE_1LANE_UP.RST_N
NetU24_B35: U24.B35(WAKE#) ; port PCIE_1LANE_UP.WAKE_N
NetU24_B36: U24.B36(CLKREQ#) ; port PCIE_1LANE_UP.CLKREQ_N
NetU24_B45: U24.B45(OVERCUR4#) ; port USB4_OVERCUR1#_3V3

Not connected (* = marked no-connect by the designer): U24 A14(NC)* A26(NC)* A43(NC)* A49(GPIO0)* B8(NC)* B13(NC)* B29(NC)* B46(GPIO1)* B47(GPIO2)* B48(GPIO3)*

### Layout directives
differential pair; differential pair class PCIE_USB_CAPS: TUSB_CAP_TX_N_26, TUSB_CAP_TX_P_26
differential pair; differential pair class TUSB_USB1: USB1_D_N, USB1_D_P, USB1_SSRX_N, USB1_SSRX_P, USB1_SSTX_N_26, USB1_SSTX_P_26
differential pair; differential pair class TUSB_USB2: USB2_D_N, USB2_D_P, USB2_SSRX_N, USB2_SSRX_P, USB2_SSTX_N_26, USB2_SSTX_P_26
differential pair; differential pair class TUSB_USB3: USB3_D_N, USB3_D_P, USB3_SSRX_N, USB3_SSRX_P, USB3_SSTX_N_26, USB3_SSTX_P_26
differential pair; differential pair class TUSB_USB4: USB4_D_N, USB4_D_P, USB4_SSRX_N, USB4_SSRX_P, USB4_SSTX_N_26, USB4_SSTX_P_26
differential pair; differential pair class TUSB_USB1_CAP: USB1_CAP_SSTX_N, USB1_CAP_SSTX_P
differential pair; differential pair class TUSB_USB2_CAP: USB2_CAP_SSTX_N, USB2_CAP_SSTX_P
differential pair; differential pair class TUSB_USB3_CAP: USB3_CAP_SSTX_N, USB3_CAP_SSTX_P
differential pair; differential pair class TUSB_USB4_CAP: USB4_CAP_SSTX_N, USB4_CAP_SSTX_P

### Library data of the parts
C113 C180-C186 C188-C199 C202-C204 C206 C207 C210-C215 C280 C283 C284 C289 C290 C297 C298 C324 C325 = C0113-A.6: as C128-C131 on sheet WIFI_BLE
C200 C208 C216 = C0158-A.3: CAP CHIP 0805 10uF 20% 50V X5R; Manufacturer: Murata Electronics; Code Arduino: C0158
C218 C219 = C0003-A.15: CAP CHIP 0201 12pF 5% 25V C0G; Manufacturer: Murata; Code Arduino: C0003
L18 = I0028-A.10: FERRITE SMD 0402 120Ohm 25% 100MHz Ferrite 2A; Manufacturer: Murata; Inductance: 120µH; DC Resistance (DCR): 55mR; Code Arduino: I0028; Value: 120µH
R189 R192 R318 = R0140-A.21: as R312-R314 on sheet WIFI_BLE
R190 = R0397-A.2: RES CHIP 0201 9k09 1% 1/20W; Manufacturer: YAGEO; Code Arduino: R0397; Power: 50mW; Temperature Coefficient: 200ppm
R191 = R0145-A.21: as R24 on sheet WIFI_BLE
R193 = R0151-A.21: RES CHIP 0201 4k7 1% 1/20W; Manufacturer: Yageo; Temperature coefficient: 200ppm; Power: 50mW; Code Arduino: A5521
R194 = R0394-A.1: RES CHIP 0402 2M 1% 1/16W; Manufacturer: YAGEO; Temperature coefficient: 100ppm; Code Arduino: R0394; Power: 62.5mW
TP6-TP12 = UT0013-A.6: Part Number: This is not a component
U24 = U0510-A.10: IC PCIe x1 Gen2 to x4 USB 3.0 converter, QFN-MR100 9x9mm; Manufacturer: Texas Instruments; Code Arduino: U0510
Y2 = X0032-A.3: CRYSTAL 48MHz tolerance 10ppm stability 20ppm load 10pF 3.2x2.5mm; Manufacturer: Kyocera; Series Resistance: 30R; ESR (Equivalent Series Resistance): 30; Code Arduino: X0032

## Sheet CAN_PHY.SchDoc: CAN PHY
size A3; Author: Silvio Navaretti; CompanyName: ARDUINO; DrawnBy: Silvio Navaretti; Engineer: Silvio Navaretti; Organization: ARDUINO; SheetNumber: 48; SheetTotal: 51; RevAuthor: Silvio Navaretti
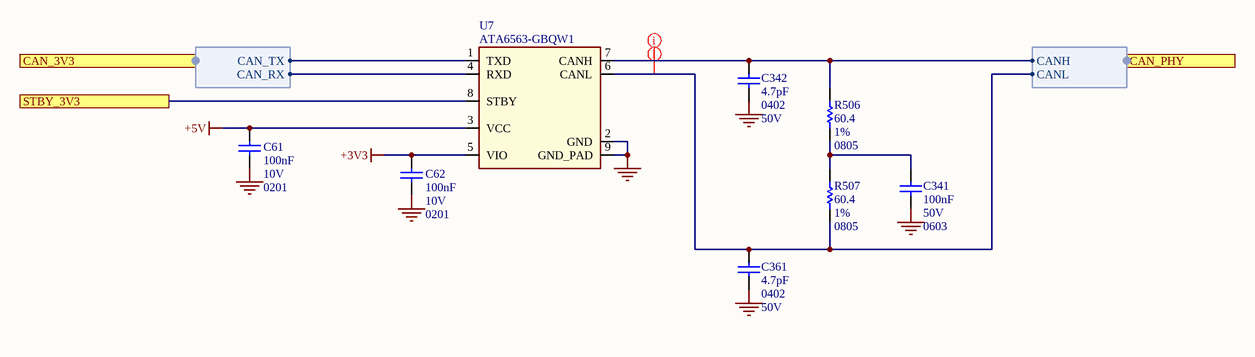
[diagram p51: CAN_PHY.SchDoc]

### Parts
C61  value 100nF  Voltage: 10V  Case Code (Imperial): 0201  [CAP-0201]  (hidden comment: CL03A104KP3NNNC)
C62  value 100nF  Voltage: 10V  Case Code (Imperial): 0201  [CAP-0201]  (hidden comment: CL03A104KP3NNNC)
C341  value 100nF  Voltage: 50V  Case Code (Imperial): 0603  [CAP-0603]  (hidden comment: 0603B104K500CT)
C342  value 4.7pF  Case Code (Imperial): 0402  Voltage: 50V  [CAP-0402]  (hidden comment: 04025A4R7DAT2A)
C361  value 4.7pF  Case Code (Imperial): 0402  Voltage: 50V  [CAP-0402]  (hidden comment: 04025A4R7DAT2A)
R506  value 60.4  Tolerance: 1%  Case Code (Imperial): 0805  [RES-0805]  (hidden comment: RT0805FRE0760R4L)
R507  value 60.4  Tolerance: 1%  Case Code (Imperial): 0805  [RES-0805]  (hidden comment: RT0805FRE0760R4L)
U7  ATA6563-GBQW1  [Microchip VDFN8 pitch 0.65mm 3x3mm exposed pad 2.4x1.6mm]

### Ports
CAN_3V3 (harness CAN), CAN_PHY (harness CAN_PHY), STBY_3V3

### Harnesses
CAN: CAN_TX, CAN_RX
CAN_PHY: CANH, CANL

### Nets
+3V3: C62.2 U7.5(VIO)
+5V: C61.2 U7.3(VCC)
GND: C61.1 C62.1 C341.2 C342.2 C361.2 U7.2(GND) U7.9(GND_PAD)
PD0: U7.4(RXD) ; port CAN_3V3.CAN_RX
PD1: U7.1(TXD) ; port CAN_3V3.CAN_TX
PI11: U7.8(STBY) ; port STBY_3V3
NetC341_1: C341.1 R506.1 R507.2
NetC342_1: C342.1 R506.2 U7.7(CANH) ; port CAN_PHY.CANH
NetC361_1: C361.1 R507.1 U7.6(CANL) ; port CAN_PHY.CANL

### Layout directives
net class HIGH_CLEARANCE: NetC342_1, NetC361_1

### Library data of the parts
C61 C62 = C0113-A.6: as C128-C131 on sheet WIFI_BLE
C341 = C0043-A.14: CAP CHIP 0603 100nF 10% 50V X7R; Manufacturer: Walsin; Code Arduino: 0015
C342 C361 = C0117-A.6: CAP CHIP 0402 4.7pF ±0.5pF 50V C0G; Manufacturer: AVX; Code Arduino: C0117; Tolerance: 4.7%
R506 R507 = R0422-A.1: RES CHIP 0805 60R4 1% 1/8W 50ppm; Manufacturer: YAGEO; Code Arduino: R0422; Power: 125mW
U7 = U0505-A.4: IC CAN FD PHY 5Mbps, VIO pin, Standby, VDFN8 3x3mm; Manufacturer: Microchip; Code Arduino: U0505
